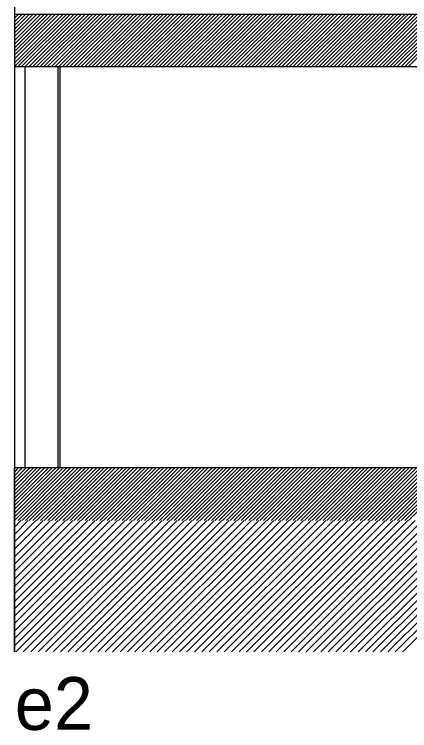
# Model space of a CAD drawing. Extents: x -4333 to -3435, y 16386 to 16556.
# Drawn here: x -3661.32 to -3658.31, y 16401.57 to 16407.02 of the extents above; entities that cross this region are included whole.
import ezdxf

# ---------------------------------------------------------------- set-up
doc = ezdxf.new("R2010")
doc.units = 0
for name, color, linetype in [('Level 1', 7, 'Continuous'), ('Level 2', 7, 'Continuous'), ('Level 57', 7, 'Continuous'), ('Level 63', 7, 'Continuous')]:
    doc.layers.add(name, color=color, linetype=linetype)

msp = doc.modelspace()

# ---------------------------------------------------------------- linework, layer by layer
at = {"layer": 'Level 1'}
for p, q in [((-3649.3724, 16407.021), (-3661.3208, 16407.0209)), ((-3649.3725, 16406.621), (-3661.3208, 16406.621)), ((-3601.343, 16403.5701), (-3661.3208, 16403.5701)), ((-3661.3208, 16402.1701), (-3661.3208, 16403.5701))]:
    msp.add_line(p, q, dxfattribs=at)
at = {"layer": 'Level 2'}
for p, q in [((-3661.3208, 16411.5051), (-3661.3208, 16402.1701)), ((-3660.976, 16406.621), (-3660.976, 16403.5701))]:
    msp.add_line(p, q, dxfattribs=at)
at = {"layer": 'Level 57'}
for p, q in [((-3661.3208, 16407.0209), (-3661.3208, 16407.0209)), ((-3661.3208, 16406.9927), (-3661.2925, 16407.0209)), ((-3661.3208, 16406.9644), (-3661.2642, 16407.0209)), ((-3661.3208, 16406.9361), (-3661.2359, 16407.0209)), ((-3661.3208, 16406.9078), (-3661.2077, 16407.0209)), ((-3661.3208, 16406.8795), (-3661.1794, 16407.0209)), ((-3661.3208, 16406.8512), (-3661.1511, 16407.0209)), ((-3661.3208, 16406.823), (-3661.1228, 16407.0209)), ((-3661.3208, 16406.7947), (-3661.0945, 16407.0209)), ((-3661.3208, 16406.7664), (-3661.0662, 16407.0209)), ((-3661.3208, 16406.7381), (-3661.038, 16407.0209)), ((-3661.3208, 16406.7098), (-3661.0097, 16407.0209)), ((-3661.3208, 16406.6815), (-3660.9814, 16407.0209)), ((-3661.3208, 16406.6532), (-3660.9531, 16407.0209)), ((-3661.3208, 16406.625), (-3660.9248, 16407.0209)), ((-3661.2965, 16406.621), (-3660.8965, 16407.0209)), ((-3661.2682, 16406.621), (-3660.8682, 16407.0209)), ((-3661.2399, 16406.621), (-3660.84, 16407.0209)), ((-3661.2117, 16406.621), (-3660.8117, 16407.0209)), ((-3661.1834, 16406.621), (-3660.7834, 16407.0209)), ((-3661.1551, 16406.621), (-3660.7551, 16407.0209)), ((-3661.1268, 16406.621), (-3660.7268, 16407.0209)), ((-3661.0985, 16406.621), (-3660.6985, 16407.0209)), ((-3661.0702, 16406.621), (-3660.6703, 16407.0209)), ((-3661.042, 16406.621), (-3660.642, 16407.0209)), ((-3661.0137, 16406.621), (-3660.6137, 16407.0209)), ((-3660.9854, 16406.621), (-3660.5854, 16407.0209)), ((-3660.9571, 16406.621), (-3660.5571, 16407.0209)), ((-3660.9288, 16406.621), (-3660.5288, 16407.0209)), ((-3660.9005, 16406.621), (-3660.5005, 16407.0209)), ((-3660.8722, 16406.621), (-3660.4723, 16407.0209)), ((-3660.844, 16406.621), (-3660.444, 16407.0209)), ((-3660.8157, 16406.621), (-3660.4157, 16407.0209)), ((-3660.7874, 16406.621), (-3660.3874, 16407.0209)), ((-3660.7591, 16406.621), (-3660.3591, 16407.0209)), ((-3660.7308, 16406.621), (-3660.3308, 16407.0209)), ((-3660.7025, 16406.621), (-3660.3026, 16407.0209)), ((-3660.6743, 16406.621), (-3660.2743, 16407.0209)), ((-3660.646, 16406.621), (-3660.246, 16407.0209)), ((-3660.6177, 16406.621), (-3660.2177, 16407.0209)), ((-3660.5894, 16406.621), (-3660.1894, 16407.0209)), ((-3660.5611, 16406.621), (-3660.1611, 16407.0209)), ((-3660.5328, 16406.621), (-3660.1329, 16407.0209)), ((-3660.5046, 16406.621), (-3660.1046, 16407.0209)), ((-3660.4763, 16406.621), (-3660.0763, 16407.0209)), ((-3660.448, 16406.621), (-3660.048, 16407.0209)), ((-3660.4197, 16406.621), (-3660.0197, 16407.0209)), ((-3660.3914, 16406.621), (-3659.9914, 16407.0209)), ((-3660.3631, 16406.621), (-3659.9631, 16407.0209)), ((-3660.3348, 16406.621), (-3659.9349, 16407.0209)), ((-3660.3066, 16406.621), (-3659.9066, 16407.0209)), ((-3660.2783, 16406.621), (-3659.8783, 16407.0209)), ((-3660.25, 16406.621), (-3659.85, 16407.0209)), ((-3660.2217, 16406.621), (-3659.8217, 16407.0209)), ((-3660.1934, 16406.621), (-3659.7934, 16407.0209)), ((-3660.1651, 16406.621), (-3659.7652, 16407.0209)), ((-3660.1369, 16406.621), (-3659.7369, 16407.0209)), ((-3660.1086, 16406.621), (-3659.7086, 16407.0209)), ((-3660.0803, 16406.621), (-3659.6803, 16407.0209)), ((-3660.052, 16406.621), (-3659.652, 16407.0209)), ((-3660.0237, 16406.621), (-3659.6237, 16407.0209)), ((-3659.9954, 16406.621), (-3659.5955, 16407.0209)), ((-3659.9672, 16406.621), (-3659.5672, 16407.0209)), ((-3659.9389, 16406.621), (-3659.5389, 16407.0209)), ((-3659.9106, 16406.621), (-3659.5106, 16407.0209)), ((-3659.8823, 16406.621), (-3659.4823, 16407.0209)), ((-3659.854, 16406.621), (-3659.454, 16407.0209)), ((-3659.8257, 16406.621), (-3659.4257, 16407.0209)), ((-3659.7974, 16406.621), (-3659.3975, 16407.0209)), ((-3659.7692, 16406.621), (-3659.3692, 16407.0209)), ((-3659.7409, 16406.621), (-3659.3409, 16407.0209)), ((-3659.7126, 16406.621), (-3659.3126, 16407.0209)), ((-3659.6843, 16406.621), (-3659.2843, 16407.0209)), ((-3659.656, 16406.621), (-3659.256, 16407.0209)), ((-3659.6277, 16406.621), (-3659.2278, 16407.0209)), ((-3659.5995, 16406.621), (-3659.1995, 16407.0209)), ((-3659.5712, 16406.621), (-3659.1712, 16407.0209)), ((-3659.5429, 16406.621), (-3659.1429, 16407.0209)), ((-3659.5146, 16406.621), (-3659.1146, 16407.0209)), ((-3659.4863, 16406.621), (-3659.0863, 16407.0209)), ((-3659.458, 16406.621), (-3659.058, 16407.0209)), ((-3659.4297, 16406.621), (-3659.0298, 16407.0209)), ((-3659.4015, 16406.621), (-3659.0015, 16407.0209)), ((-3659.3732, 16406.621), (-3658.9732, 16407.0209)), ((-3659.3449, 16406.621), (-3658.9449, 16407.0209)), ((-3659.3166, 16406.621), (-3658.9166, 16407.0209)), ((-3659.2883, 16406.621), (-3658.8883, 16407.0209)), ((-3659.26, 16406.621), (-3658.8601, 16407.0209)), ((-3659.2318, 16406.621), (-3658.8318, 16407.0209)), ((-3659.2035, 16406.621), (-3658.8035, 16407.0209)), ((-3659.1752, 16406.621), (-3658.7752, 16407.0209)), ((-3659.1469, 16406.621), (-3658.7469, 16407.0209)), ((-3659.1186, 16406.621), (-3658.7186, 16407.0209)), ((-3659.0903, 16406.621), (-3658.6904, 16407.0209)), ((-3659.0621, 16406.621), (-3658.6621, 16407.0209)), ((-3659.0338, 16406.621), (-3658.6338, 16407.0209)), ((-3659.0055, 16406.621), (-3658.6055, 16407.0209)), ((-3658.9772, 16406.621), (-3658.5772, 16407.0209)), ((-3658.9489, 16406.621), (-3658.5489, 16407.0209)), ((-3658.9206, 16406.621), (-3658.5206, 16407.0209)), ((-3658.8923, 16406.621), (-3658.4924, 16407.0209)), ((-3658.8641, 16406.621), (-3658.4641, 16407.0209)), ((-3658.8358, 16406.621), (-3658.4358, 16407.0209)), ((-3658.8075, 16406.621), (-3658.4075, 16407.0209)), ((-3658.7792, 16406.621), (-3658.3792, 16407.0209)), ((-3658.7509, 16406.621), (-3658.3509, 16407.0209)), ((-3658.7226, 16406.621), (-3658.3227, 16407.021)), ((-3658.6944, 16406.621), (-3658.2944, 16407.021)), ((-3658.6661, 16406.621), (-3658.2661, 16407.021)), ((-3658.6378, 16406.621), (-3658.2378, 16407.021)), ((-3658.6095, 16406.621), (-3658.2095, 16407.021)), ((-3658.5812, 16406.621), (-3658.1812, 16407.021)), ((-3658.5529, 16406.621), (-3658.153, 16407.021)), ((-3658.5247, 16406.621), (-3658.1247, 16407.021)), ((-3658.4964, 16406.621), (-3658.0964, 16407.021)), ((-3658.4681, 16406.621), (-3658.0681, 16407.021)), ((-3658.4398, 16406.621), (-3658.0398, 16407.021)), ((-3658.4115, 16406.621), (-3658.0115, 16407.021)), ((-3658.3832, 16406.621), (-3657.9832, 16407.021)), ((-3658.3549, 16406.621), (-3657.955, 16407.021)), ((-3658.3267, 16406.621), (-3657.9267, 16407.021)), ((-3661.3208, 16403.5661), (-3661.3168, 16403.5701)), ((-3661.3208, 16403.5378), (-3661.2885, 16403.5701)), ((-3661.3208, 16403.5095), (-3661.2602, 16403.5701)), ((-3661.3208, 16403.4812), (-3661.2319, 16403.5701)), ((-3661.3208, 16403.4529), (-3661.2036, 16403.5701)), ((-3661.3208, 16403.4246), (-3661.1753, 16403.5701)), ((-3661.3208, 16403.3963), (-3661.1471, 16403.5701)), ((-3661.3208, 16403.3681), (-3661.1188, 16403.5701)), ((-3661.3208, 16403.3398), (-3661.0905, 16403.5701)), ((-3661.3208, 16403.3115), (-3661.0622, 16403.5701)), ((-3661.3208, 16403.2832), (-3661.0339, 16403.5701)), ((-3661.3208, 16403.2549), (-3661.0056, 16403.5701)), ((-3661.3208, 16403.2266), (-3660.9774, 16403.5701)), ((-3661.3208, 16403.1984), (-3660.9491, 16403.5701)), ((-3661.3208, 16403.1701), (-3660.9208, 16403.5701)), ((-3661.2925, 16403.1701), (-3660.8925, 16403.5701)), ((-3661.2642, 16403.1701), (-3660.8642, 16403.5701)), ((-3661.2359, 16403.1701), (-3660.8359, 16403.5701)), ((-3661.2076, 16403.1701), (-3660.8076, 16403.5701)), ((-3661.1794, 16403.1701), (-3660.7794, 16403.5701)), ((-3661.1511, 16403.1701), (-3660.7511, 16403.5701)), ((-3661.1228, 16403.1701), (-3660.7228, 16403.5701)), ((-3661.0945, 16403.1701), (-3660.6945, 16403.5701)), ((-3661.0662, 16403.1701), (-3660.6662, 16403.5701)), ((-3661.0379, 16403.1701), (-3660.6379, 16403.5701)), ((-3661.0097, 16403.1701), (-3660.6097, 16403.5701)), ((-3660.9814, 16403.1701), (-3660.5814, 16403.5701)), ((-3660.9531, 16403.1701), (-3660.5531, 16403.5701)), ((-3660.9248, 16403.1701), (-3660.5248, 16403.5701)), ((-3660.8965, 16403.1701), (-3660.4965, 16403.5701)), ((-3660.8682, 16403.1701), (-3660.4682, 16403.5701)), ((-3660.84, 16403.1701), (-3660.44, 16403.5701)), ((-3660.8117, 16403.1701), (-3660.4117, 16403.5701)), ((-3660.7834, 16403.1701), (-3660.3834, 16403.5701)), ((-3660.7551, 16403.1701), (-3660.3551, 16403.5701)), ((-3660.7268, 16403.1701), (-3660.3268, 16403.5701)), ((-3660.6985, 16403.1701), (-3660.2985, 16403.5701)), ((-3660.6702, 16403.1701), (-3660.2702, 16403.5701)), ((-3660.642, 16403.1701), (-3660.242, 16403.5701)), ((-3660.6137, 16403.1701), (-3660.2137, 16403.5701)), ((-3660.5854, 16403.1701), (-3660.1854, 16403.5701)), ((-3660.5571, 16403.1701), (-3660.1571, 16403.5701)), ((-3660.5288, 16403.1701), (-3660.1288, 16403.5701)), ((-3660.5005, 16403.1701), (-3660.1005, 16403.5701)), ((-3660.4723, 16403.1701), (-3660.0723, 16403.5701)), ((-3660.444, 16403.1701), (-3660.044, 16403.5701)), ((-3660.4157, 16403.1701), (-3660.0157, 16403.5701)), ((-3660.3874, 16403.1701), (-3659.9874, 16403.5701)), ((-3660.3591, 16403.1701), (-3659.9591, 16403.5701)), ((-3660.3308, 16403.1701), (-3659.9308, 16403.5701)), ((-3660.3026, 16403.1701), (-3659.9026, 16403.5701)), ((-3660.2743, 16403.1701), (-3659.8743, 16403.5701)), ((-3660.246, 16403.1701), (-3659.846, 16403.5701)), ((-3660.2177, 16403.1701), (-3659.8177, 16403.5701)), ((-3660.1894, 16403.1701), (-3659.7894, 16403.5701)), ((-3660.1611, 16403.1701), (-3659.7611, 16403.5701)), ((-3660.1328, 16403.1701), (-3659.7328, 16403.5701)), ((-3660.1046, 16403.1701), (-3659.7046, 16403.5701)), ((-3660.0763, 16403.1701), (-3659.6763, 16403.5701)), ((-3660.048, 16403.1701), (-3659.648, 16403.5701)), ((-3660.0197, 16403.1701), (-3659.6197, 16403.5701)), ((-3659.9914, 16403.1701), (-3659.5914, 16403.5701)), ((-3659.9631, 16403.1701), (-3659.5631, 16403.5701)), ((-3659.9349, 16403.1701), (-3659.5349, 16403.5701)), ((-3659.9066, 16403.1701), (-3659.5066, 16403.5701)), ((-3659.8783, 16403.1701), (-3659.4783, 16403.5701)), ((-3659.85, 16403.1701), (-3659.45, 16403.5701)), ((-3659.8217, 16403.1701), (-3659.4217, 16403.5701)), ((-3659.7934, 16403.1701), (-3659.3934, 16403.5701)), ((-3659.7652, 16403.1701), (-3659.3652, 16403.5701)), ((-3659.7369, 16403.1701), (-3659.3369, 16403.5701)), ((-3659.7086, 16403.1701), (-3659.3086, 16403.5701)), ((-3659.6803, 16403.1701), (-3659.2803, 16403.5701)), ((-3659.652, 16403.1701), (-3659.252, 16403.5701)), ((-3659.6237, 16403.1701), (-3659.2237, 16403.5701)), ((-3659.5954, 16403.1701), (-3659.1954, 16403.5701)), ((-3659.5672, 16403.1701), (-3659.1672, 16403.5701)), ((-3659.5389, 16403.1701), (-3659.1389, 16403.5701)), ((-3659.5106, 16403.1701), (-3659.1106, 16403.5701)), ((-3659.4823, 16403.1701), (-3659.0823, 16403.5701)), ((-3659.454, 16403.1701), (-3659.054, 16403.5701)), ((-3659.4257, 16403.1701), (-3659.0257, 16403.5701)), ((-3659.3975, 16403.1701), (-3658.9975, 16403.5701)), ((-3659.3692, 16403.1701), (-3658.9692, 16403.5701)), ((-3659.3409, 16403.1701), (-3658.9409, 16403.5701)), ((-3659.3126, 16403.1701), (-3658.9126, 16403.5701)), ((-3659.2843, 16403.1701), (-3658.8843, 16403.5701)), ((-3659.256, 16403.1701), (-3658.856, 16403.5701)), ((-3659.2277, 16403.1701), (-3658.8277, 16403.5701)), ((-3659.1995, 16403.1701), (-3658.7995, 16403.5701)), ((-3659.1712, 16403.1701), (-3658.7712, 16403.5701)), ((-3659.1429, 16403.1701), (-3658.7429, 16403.5701)), ((-3659.1146, 16403.1701), (-3658.7146, 16403.5701)), ((-3659.0863, 16403.1701), (-3658.6863, 16403.5701)), ((-3659.058, 16403.1701), (-3658.658, 16403.5701)), ((-3659.0298, 16403.1701), (-3658.6298, 16403.5701)), ((-3659.0015, 16403.1701), (-3658.6015, 16403.5701)), ((-3658.9732, 16403.1701), (-3658.5732, 16403.5701)), ((-3658.9449, 16403.1701), (-3658.5449, 16403.5701)), ((-3658.9166, 16403.1701), (-3658.5166, 16403.5701)), ((-3658.8883, 16403.1701), (-3658.4883, 16403.5701)), ((-3658.8601, 16403.1701), (-3658.4601, 16403.5701)), ((-3658.8318, 16403.1701), (-3658.4318, 16403.5701)), ((-3658.8035, 16403.1701), (-3658.4035, 16403.5701)), ((-3658.7752, 16403.1701), (-3658.3752, 16403.5701)), ((-3658.7469, 16403.1701), (-3658.3469, 16403.5701)), ((-3658.7186, 16403.1701), (-3658.3186, 16403.5701)), ((-3658.6903, 16403.1701), (-3658.2903, 16403.5701)), ((-3658.6621, 16403.1701), (-3658.2621, 16403.5701)), ((-3658.6338, 16403.1701), (-3658.2338, 16403.5701)), ((-3658.6055, 16403.1701), (-3658.2055, 16403.5701)), ((-3658.5772, 16403.1701), (-3658.1772, 16403.5701)), ((-3658.5489, 16403.1701), (-3658.1489, 16403.5701)), ((-3658.5206, 16403.1701), (-3658.1206, 16403.5701)), ((-3658.4924, 16403.1701), (-3658.0924, 16403.5701)), ((-3658.4641, 16403.1701), (-3658.0641, 16403.5701)), ((-3658.4358, 16403.1701), (-3658.0358, 16403.5701)), ((-3658.4075, 16403.1701), (-3658.0075, 16403.5701)), ((-3658.3792, 16403.1701), (-3657.9792, 16403.5701)), ((-3658.3509, 16403.1701), (-3657.9509, 16403.5701)), ((-3658.3227, 16403.1701), (-3657.9227, 16403.5701)), ((-3661.3208, 16403.1202), (-3661.2709, 16403.1701)), ((-3661.3208, 16403.0637), (-3661.2144, 16403.1701)), ((-3661.3208, 16403.0071), (-3661.1578, 16403.1701)), ((-3661.3208, 16402.9505), (-3661.1012, 16403.1701)), ((-3661.3208, 16402.894), (-3661.0447, 16403.1701)), ((-3661.3208, 16402.8374), (-3660.9881, 16403.1701)), ((-3661.3208, 16402.7808), (-3660.9315, 16403.1701)), ((-3661.3208, 16402.7242), (-3660.875, 16403.1701)), ((-3661.3208, 16402.6677), (-3660.8184, 16403.1701)), ((-3661.3208, 16402.6111), (-3660.7618, 16403.1701)), ((-3661.3208, 16402.5545), (-3660.7053, 16403.1701)), ((-3661.3208, 16402.498), (-3660.6487, 16403.1701)), ((-3661.3208, 16402.4414), (-3660.5921, 16403.1701)), ((-3661.3208, 16402.3848), (-3660.5355, 16403.1701)), ((-3661.3208, 16402.3283), (-3660.479, 16403.1701)), ((-3661.3208, 16402.2717), (-3660.4224, 16403.1701)), ((-3661.3208, 16402.2151), (-3660.3658, 16403.1701)), ((-3661.3208, 16403.1701), (-3661.3208, 16403.1701)), ((-3661.3093, 16402.1701), (-3660.3093, 16403.1701)), ((-3661.2527, 16402.1701), (-3660.2527, 16403.1701)), ((-3661.1961, 16402.1701), (-3660.1961, 16403.1701)), ((-3661.1396, 16402.1701), (-3660.1396, 16403.1701)), ((-3661.083, 16402.1701), (-3660.083, 16403.1701)), ((-3661.0264, 16402.1701), (-3660.0264, 16403.1701)), ((-3660.9699, 16402.1701), (-3659.9699, 16403.1701)), ((-3660.9133, 16402.1701), (-3659.9133, 16403.1701)), ((-3660.8567, 16402.1701), (-3659.8567, 16403.1701)), ((-3660.8002, 16402.1701), (-3659.8002, 16403.1701)), ((-3660.7436, 16402.1701), (-3659.7436, 16403.1701)), ((-3660.687, 16402.1701), (-3659.687, 16403.1701)), ((-3660.6305, 16402.1701), (-3659.6305, 16403.1701)), ((-3660.5739, 16402.1701), (-3659.5739, 16403.1701)), ((-3660.5173, 16402.1701), (-3659.5173, 16403.1701)), ((-3660.4607, 16402.1701), (-3659.4607, 16403.1701)), ((-3660.4042, 16402.1701), (-3659.4042, 16403.1701)), ((-3660.3476, 16402.1701), (-3659.3476, 16403.1701)), ((-3660.291, 16402.1701), (-3659.291, 16403.1701)), ((-3660.2345, 16402.1701), (-3659.2345, 16403.1701)), ((-3660.1779, 16402.1701), (-3659.1779, 16403.1701)), ((-3660.1213, 16402.1701), (-3659.1213, 16403.1701)), ((-3660.0648, 16402.1701), (-3659.0648, 16403.1701)), ((-3660.0082, 16402.1701), (-3659.0082, 16403.1701)), ((-3659.9516, 16402.1701), (-3658.9516, 16403.1701)), ((-3659.8951, 16402.1701), (-3658.8951, 16403.1701)), ((-3659.8385, 16402.1701), (-3658.8385, 16403.1701)), ((-3659.7819, 16402.1701), (-3658.7819, 16403.1701)), ((-3659.7254, 16402.1701), (-3658.7254, 16403.1701)), ((-3659.6688, 16402.1701), (-3658.6688, 16403.1701)), ((-3659.6122, 16402.1701), (-3658.6122, 16403.1701)), ((-3659.5556, 16402.1701), (-3658.5556, 16403.1701)), ((-3659.4991, 16402.1701), (-3658.4991, 16403.1701)), ((-3659.4425, 16402.1701), (-3658.4425, 16403.1701)), ((-3659.3859, 16402.1701), (-3658.3859, 16403.1701)), ((-3659.3294, 16402.1701), (-3658.3294, 16403.1701)), ((-3659.2728, 16402.1701), (-3658.2728, 16403.1701)), ((-3659.2162, 16402.1701), (-3658.2162, 16403.1701)), ((-3659.1597, 16402.1701), (-3658.1597, 16403.1701)), ((-3659.1031, 16402.1701), (-3658.1031, 16403.1701)), ((-3659.0465, 16402.1701), (-3658.0465, 16403.1701)), ((-3658.99, 16402.1701), (-3657.99, 16403.1701)), ((-3658.9334, 16402.1701), (-3657.9334, 16403.1701)), ((-3658.8768, 16402.1701), (-3657.8768, 16403.1701)), ((-3658.8203, 16402.1701), (-3657.8203, 16403.1701)), ((-3658.7637, 16402.1701), (-3657.7637, 16403.1701)), ((-3658.7071, 16402.1701), (-3657.7071, 16403.1701)), ((-3658.6506, 16402.1701), (-3657.6506, 16403.1701)), ((-3658.594, 16402.1701), (-3657.594, 16403.1701)), ((-3658.5374, 16402.1701), (-3657.5374, 16403.1701)), ((-3658.4808, 16402.1701), (-3657.4808, 16403.1701)), ((-3658.4243, 16402.1701), (-3657.4243, 16403.1701)), ((-3658.3677, 16402.1701), (-3657.3677, 16403.1701))]:
    msp.add_line(p, q, dxfattribs=at)
at = {"layer": 'Level 63'}
for p, q in [((-3661.2409, 16406.621), (-3661.2409, 16403.5701)), ((-3660.991, 16406.621), (-3660.991, 16403.5701))]:
    msp.add_line(p, q, dxfattribs=at)

# ---------------------------------------------------------------- texts
at = {"layer": 'Level 2'}
msp.add_text('e2', height=0.4, rotation=0.2978, dxfattribs=at).set_placement((-3661.3168, 16401.5758))

doc.saveas('drawing.dxf')
